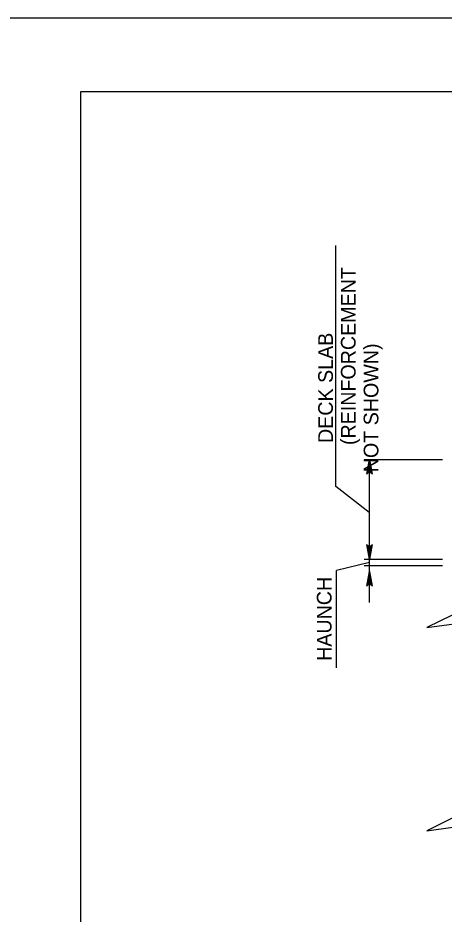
# Model space of a CAD drawing. Extents: x 640009 to 641706, y 298547 to 299735.
# Drawn here: x 640877.6 to 640964.7, y 299552.2 to 299735.2 of the extents above; entities that cross this region are included whole.
import ezdxf

# ---------------------------------------------------------------- set-up
doc = ezdxf.new("R2010")
doc.units = 0
doc.layers.add('1', color=7, linetype='Continuous')
doc.layers.add('PLT-BNDY', color=7, linetype='Continuous')

msp = doc.modelspace()

# ---------------------------------------------------------------- linework, layer by layer
at = {"layer": '1'}
for p, q in [((640890.47, 299156.17), (640890.47, 299720.17)), ((640890.47, 299720.17), (641676.47, 299720.17)), ((640890.47, 299156.17), (640890.47, 299720.17)), ((640890.47, 299720.17), (641676.47, 299720.17)), ((640942.57, 299639.53), (640942.57, 299688.7)), ((640948.31, 299645), (640964.35, 299645)), ((640949.43, 299624.68), (640949.43, 299645)), ((640949.35, 299634.19), (640942.57, 299639.53)), ((640948.31, 299624.68), (640964.35, 299624.68)), ((640949.43, 299615.85), (640949.43, 299624.68)), ((640949.43, 299623.99), (640942.66, 299622.34)), ((640942.66, 299602.5), (640942.66, 299622.34)), ((640948.31, 299623.41), (640964.35, 299623.41))]:
    msp.add_line(p, q, dxfattribs=at)
for points in [[(640949.43, 299645), (640949.99, 299642.02), (640949.91, 299642.13), (640949.83, 299642.25), (640949.73, 299642.31), (640949.63, 299642.37), (640949.53, 299642.38), (640949.43, 299642.4), (640949.33, 299642.38), (640949.23, 299642.37), (640949.13, 299642.31), (640949.03, 299642.25), (640948.95, 299642.13), (640948.87, 299642.02), (640949.43, 299645), (640948.95, 299642.13), (640949.03, 299642.25), (640949.43, 299645), (640949.13, 299642.31), (640949.23, 299642.37), (640949.43, 299645), (640949.33, 299642.38), (640949.43, 299642.4), (640949.43, 299645), (640949.53, 299642.38), (640949.63, 299642.37), (640949.43, 299645), (640949.73, 299642.31), (640949.83, 299642.25), (640949.43, 299645), (640949.91, 299642.13)], [(640949.43, 299624.68), (640948.87, 299627.66), (640948.95, 299627.55), (640949.03, 299627.43), (640949.13, 299627.37), (640949.23, 299627.31), (640949.33, 299627.3), (640949.43, 299627.28), (640949.53, 299627.3), (640949.63, 299627.31), (640949.73, 299627.37), (640949.83, 299627.43), (640949.91, 299627.55), (640949.99, 299627.66), (640949.43, 299624.68), (640949.91, 299627.55), (640949.83, 299627.43), (640949.43, 299624.68), (640949.73, 299627.37), (640949.63, 299627.31), (640949.43, 299624.68), (640949.53, 299627.3), (640949.43, 299627.28), (640949.43, 299624.68), (640949.33, 299627.3), (640949.23, 299627.31), (640949.43, 299624.68), (640949.13, 299627.37), (640949.03, 299627.43), (640949.43, 299624.68), (640948.95, 299627.55)], [(640949.43, 299622.14), (640949.99, 299619.16), (640949.91, 299619.27), (640949.83, 299619.39), (640949.73, 299619.45), (640949.63, 299619.51), (640949.53, 299619.52), (640949.43, 299619.54), (640949.33, 299619.52), (640949.23, 299619.51), (640949.13, 299619.45), (640949.03, 299619.39), (640948.95, 299619.27), (640948.87, 299619.16), (640949.43, 299622.14), (640948.95, 299619.27), (640949.03, 299619.39), (640949.43, 299622.14), (640949.13, 299619.45), (640949.23, 299619.51), (640949.43, 299622.14), (640949.33, 299619.52), (640949.43, 299619.54), (640949.43, 299622.14), (640949.53, 299619.52), (640949.63, 299619.51), (640949.43, 299622.14), (640949.73, 299619.45), (640949.83, 299619.39), (640949.43, 299622.14), (640949.91, 299619.27)], [(640966.29, 299613.25), (640961.1, 299610.72), (640971.25, 299612.1), (640966.29, 299609.73)], [(640966.29, 299571.78), (640961.1, 299569.24), (640971.25, 299570.62), (640966.29, 299568.26)]]:
    msp.add_lwpolyline(points, dxfattribs=at)
at = {"layer": 'PLT-BNDY'}
msp.add_lwpolyline([(640850.47, 299735.17), (641691.47, 299735.17), (641691.47, 299141.17), (640850.47, 299141.17)], close=True, dxfattribs=at)

# ---------------------------------------------------------------- texts
at = {"layer": '1'}
for s, p in [('(REINFORCEMENT', (640946.58, 299647.97)), ('DECK SLAB', (640941.94, 299648.39)), ('   NOT SHOWN)', (640951.23, 299639.08)), ('HAUNCH', (640941.66, 299603.91))]:
    msp.add_text(s, height=3, rotation=90, dxfattribs=at).set_placement(p)

doc.saveas('drawing.dxf')
